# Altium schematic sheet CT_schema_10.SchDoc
size 387 x 385 mm
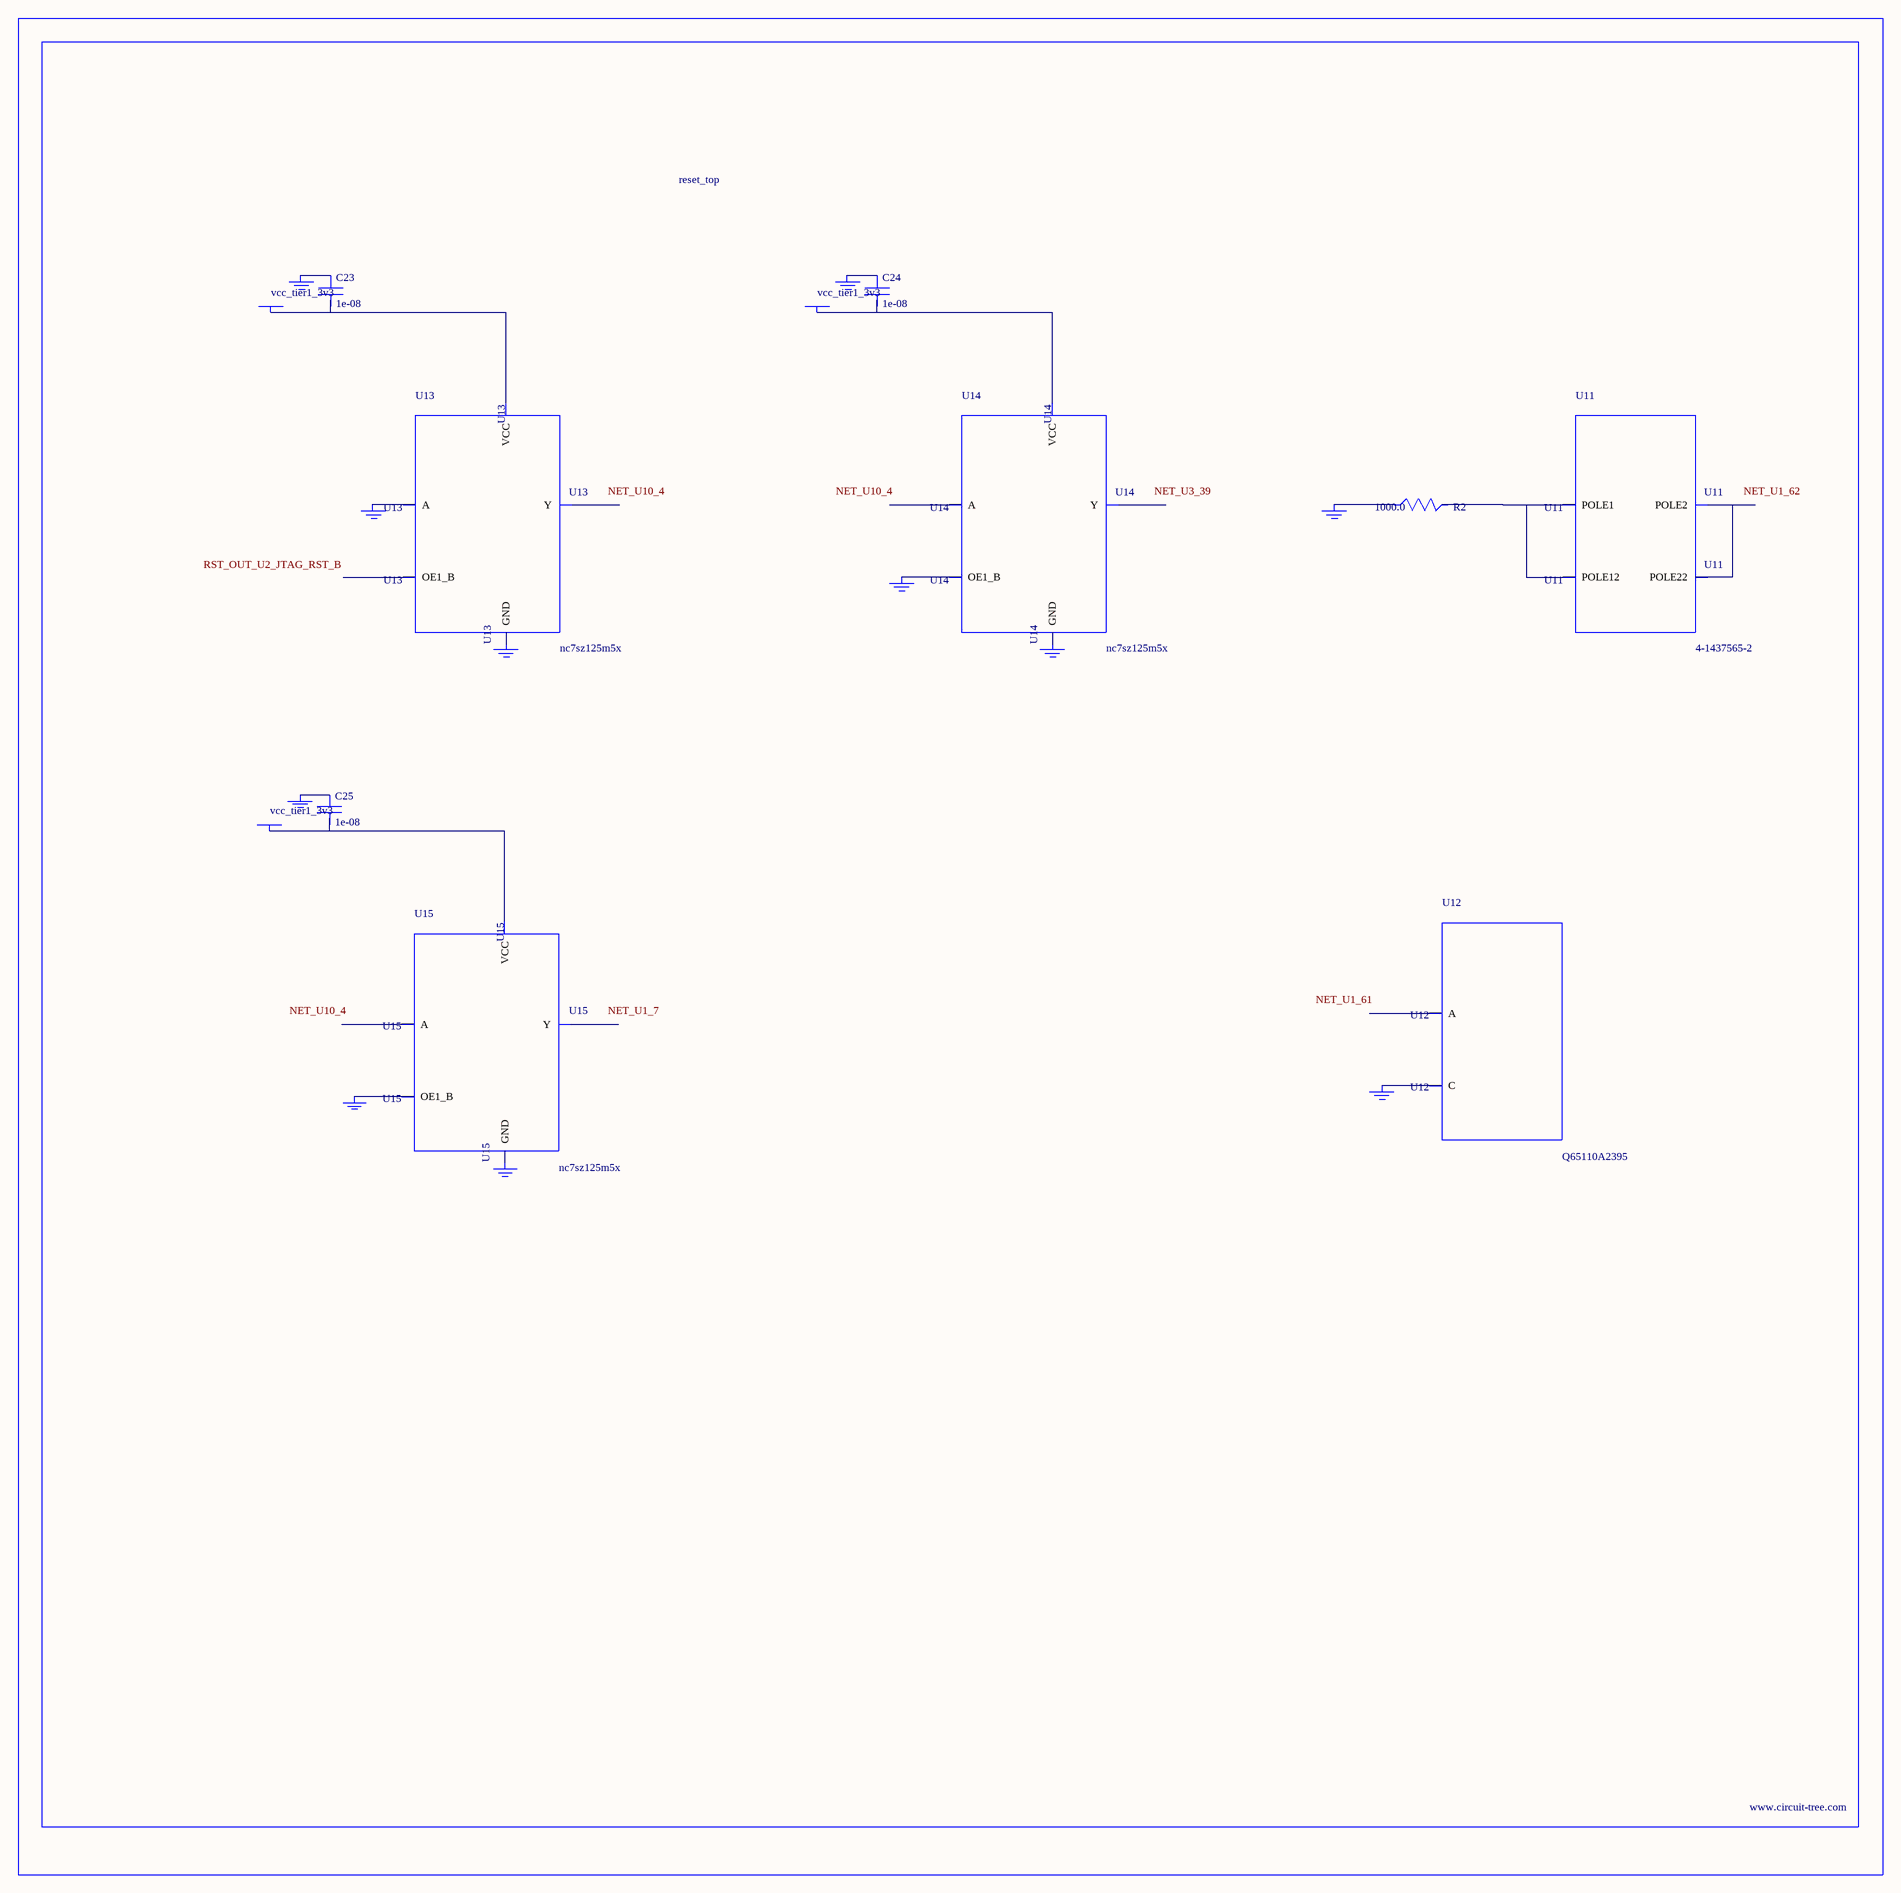
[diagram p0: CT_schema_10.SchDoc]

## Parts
BORDER9  (no value)
C23  1e-08  [C0402]
C24  1e-08  [C0402]
C25  1e-08  [C0402]
GND_INSTANCE_9_0  (no value)
GND_INSTANCE_9_1  (no value)
GND_INSTANCE_9_2  (no value)
GND_INSTANCE_9_3  (no value)
GND_INSTANCE_9_4  (no value)
GND_INSTANCE_9_5  (no value)
GND_INSTANCE_9_6  (no value)
GND_INSTANCE_9_7  (no value)
GND_INSTANCE_9_8  (no value)
GND_INSTANCE_9_9  (no value)
GND_INSTANCE_9_10  (no value)
POWER_INSTANCE_9_0  vcc_tier1_3v3
POWER_INSTANCE_9_1  vcc_tier1_3v3
POWER_INSTANCE_9_2  vcc_tier1_3v3
R2  1000.0  [R0603]
U11  4-1437565-2  [SW_4-1437565-2]
U12  Q65110A2395  [LGM67K-G1J2-24-Z]
U13  nc7sz125m5x  [NC7SZ125M5X]
U14  nc7sz125m5x  [NC7SZ125M5X]
U15  nc7sz125m5x  [NC7SZ125M5X]

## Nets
NetC23_1: C23.1 GND_INSTANCE_9_2.0(GND)
NetC23_2: C23.2 POWER_INSTANCE_9_0.0(PWR) U13.5(VCC)
NetC24_1: C24.1 GND_INSTANCE_9_5.0(GND)
NetC24_2: C24.2 POWER_INSTANCE_9_1.0(PWR) U14.5(VCC)
NetC25_1: C25.1 GND_INSTANCE_9_8.0(GND)
NetC25_2: C25.2 POWER_INSTANCE_9_2.0(PWR) U15.5(VCC)
NetGND_INSTANCE_9_0_0: GND_INSTANCE_9_0.0(GND) R2.1
NetGND_INSTANCE_9_1_0: GND_INSTANCE_9_1.0(GND) U12.C
NetGND_INSTANCE_9_3_0: GND_INSTANCE_9_3.0(GND) U13.2(A)
NetGND_INSTANCE_9_4_0: GND_INSTANCE_9_4.0(GND) U13.3(GND)
NetGND_INSTANCE_9_6_0: GND_INSTANCE_9_6.0(GND) U14.1(OE1_B)
NetGND_INSTANCE_9_7_0: GND_INSTANCE_9_7.0(GND) U14.3(GND)
NetGND_INSTANCE_9_9_0: GND_INSTANCE_9_9.0(GND) U15.1(OE1_B)
NetGND_INSTANCE_9_10_0: GND_INSTANCE_9_10.0(GND) U15.3(GND)
NetR2_2: R2.2 U11.1(POLE1) U11.2(POLE12)
NetU11_3: U11.3(POLE2) U11.4(POLE22)

Not connected (* = marked no-connect by the designer): U12 A; U13 1(OE1_B) 4(Y); U14 2(A) 4(Y); U15 2(A) 4(Y)

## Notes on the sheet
- Labels drawn without touching a wire or pin: NET_U1_7, NET_U1_61, NET_U1_62, NET_U3_39, NET_U10_4, RST_OUT_U2_JTAG_RST_B

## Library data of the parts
BORDER9 = BORDER_PAGE9
C23-C25 = C0402C103K3RAC
GND_INSTANCE_9_0-GND_INSTANCE_9_10 = GND
POWER_INSTANCE_9_0-POWER_INSTANCE_9_2 = PWR
R2 = RC0603JR-071KL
